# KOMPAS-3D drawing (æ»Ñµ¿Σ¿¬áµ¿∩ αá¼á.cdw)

Referenced files: 1.cdw
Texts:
  ПЛК.02.01.01.00 СП
  Рама сварная
  Назаров Андрей
  Noncommercial version
  Документация
  Сборочный чертеж
  Детали
  Швеллер 10х534 ГОСТ 8240-89
  Швеллер 10х587 ГОСТ 8240-89
  Швеллер 10х323 ГОСТ 8240-89
  Швеллер 10х145 ГОСТ 8240-89
  Платика 53х53х5
  Платика 80х63х6
  Ст 3
  Ст3
  ПСК.34.00.00 СП-
  ПЛК.02.01.01.00 СБ
  ПЛК.02.01.01.01
  Вавилин В.в
  Чаша
  Стандартные изделия
  Гайки ГОСТ 5950-70
Dimensions and other numbers on the sheet: 1:1; 1; 2; 3; 4; 5; 6; 7; 8; 9; 0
